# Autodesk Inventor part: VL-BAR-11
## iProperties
Created: 2005-08
Part Number: VL-BAR-11
Document SubType Name: Sheet Metal
Density: 1 g/cm^3
Mass: 1.85981 g
Surface Area: 36.0583 cm^2
Volume: 1.85981 cm^3
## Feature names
1. Rectangular Pattern1
2. Plate1
